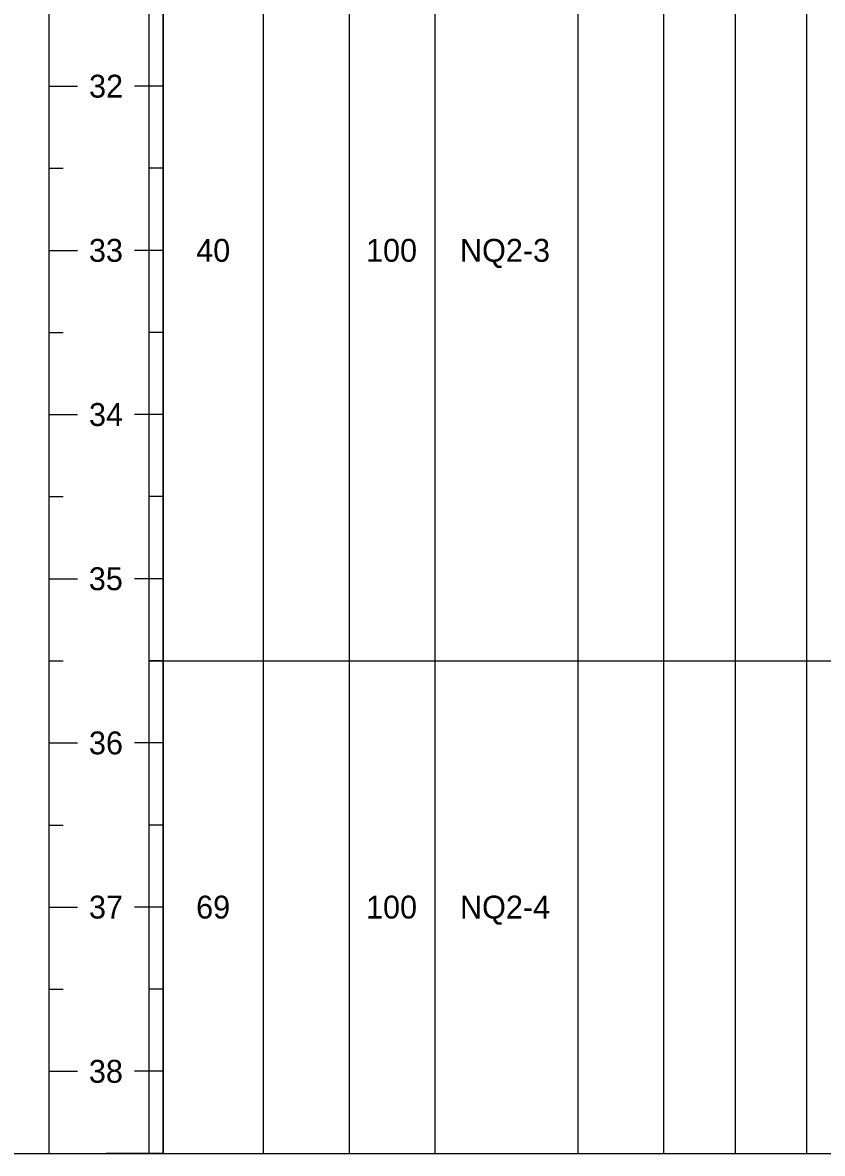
# Model space of a CAD drawing. Extents: x 0 to 0.83, y -0.65 to 1.27.
# Drawn here: x 0.3715 to 0.6046, y -0.6457 to -0.3163 of the extents above; entities that cross this region are included whole.
import ezdxf

# ---------------------------------------------------------------- set-up
doc = ezdxf.new("R2010")
doc.units = 0

msp = doc.modelspace()

# ---------------------------------------------------------------- linework, layer by layer
for points in [[(0.4125, 1.22083), (0.4125, -0.64575)], [(0.4125, 1.22083), (0.4125, -0.64575)], [(0.44167, 1.22083), (0.44167, -0.64575)], [(0.46667, 1.22083), (0.46667, -0.64575)], [(0.49167, 1.22083), (0.49167, -0.64575)], [(0.53333, 1.22083), (0.53333, -0.64575)], [(0.55833, 1.22083), (0.55833, -0.64575)], [(0.57917, 1.20833), (0.57917, -0.64575)], [(0.6, 1.20833), (0.6, -0.64575)], [(0.37917, 1.19583), (0.37917, -0.64575)], [(0.40833, -0.26308), (0.40833, -0.50225)], [(0.37917, -0.33483), (0.3875, -0.33483)], [(0.37917, -0.33483), (0.38333, -0.33483)], [(0.4125, -0.33483), (0.40417, -0.33483)], [(0.4125, -0.33483), (0.40833, -0.33483)], [(0.37917, -0.35875), (0.38333, -0.35875)], [(0.4125, -0.35875), (0.40833, -0.35875)], [(0.37917, -0.38267), (0.3875, -0.38267)], [(0.37917, -0.38267), (0.38333, -0.38267)], [(0.4125, -0.38267), (0.40417, -0.38267)], [(0.4125, -0.38267), (0.40833, -0.38267)], [(0.37917, -0.40658), (0.38333, -0.40658)], [(0.4125, -0.40658), (0.40833, -0.40658)], [(0.37917, -0.4305), (0.3875, -0.4305)], [(0.37917, -0.4305), (0.38333, -0.4305)], [(0.4125, -0.4305), (0.40417, -0.4305)], [(0.4125, -0.4305), (0.40833, -0.4305)], [(0.37917, -0.45442), (0.38333, -0.45442)], [(0.4125, -0.45442), (0.40833, -0.45442)], [(0.37917, -0.47833), (0.3875, -0.47833)], [(0.37917, -0.47833), (0.38333, -0.47833)], [(0.4125, -0.47833), (0.40417, -0.47833)], [(0.4125, -0.47833), (0.40833, -0.47833)], [(0.37917, -0.50225), (0.38333, -0.50225)], [(0.40833, -0.50225), (0.4125, -0.50225)], [(0.40833, -0.50225), (0.40833, -0.64575)], [(0.40833, -0.50225), (0.4125, -0.50225)], [(0.4125, -0.50225), (0.40833, -0.50225)], [(0.4125, -0.50225), (0.44167, -0.50225)], [(0.44167, -0.50225), (0.46667, -0.50225)], [(0.46667, -0.50225), (0.49167, -0.50225)], [(0.49167, -0.50225), (0.53333, -0.50225)], [(0.53333, -0.50225), (0.55833, -0.50225)], [(0.55833, -0.50225), (0.57917, -0.50225)], [(0.57917, -0.50225), (0.6, -0.50225)], [(0.6, -0.50225), (0.62083, -0.50225)], [(0.37917, -0.52617), (0.3875, -0.52617)], [(0.37917, -0.52617), (0.38333, -0.52617)], [(0.4125, -0.52617), (0.40417, -0.52617)], [(0.4125, -0.52617), (0.40833, -0.52617)], [(0.37917, -0.55008), (0.38333, -0.55008)], [(0.4125, -0.55008), (0.40833, -0.55008)], [(0.37917, -0.574), (0.3875, -0.574)], [(0.37917, -0.574), (0.38333, -0.574)], [(0.4125, -0.574), (0.40417, -0.574)], [(0.4125, -0.574), (0.40833, -0.574)], [(0.37917, -0.59792), (0.38333, -0.59792)], [(0.4125, -0.59792), (0.40833, -0.59792)], [(0.37917, -0.62183), (0.3875, -0.62183)], [(0.37917, -0.62183), (0.38333, -0.62183)], [(0.4125, -0.62183), (0.40417, -0.62183)], [(0.4125, -0.62183), (0.40833, -0.62183)], [(0.33333, -0.64575), (0.37917, -0.64575)], [(0.37917, -0.64575), (0.4125, -0.64575)], [(0.37917, -0.64575), (0.38333, -0.64575)], [(0.37917, -0.64575), (0.39583, -0.64575)], [(0.4125, -0.64575), (0.39583, -0.64575)], [(0.40833, -0.64575), (0.4125, -0.64575)], [(0.40833, -0.64575), (0.4125, -0.64575)], [(0.4125, -0.64575), (0.40833, -0.64575)], [(0.4125, -0.64575), (0.44167, -0.64575)], [(0.44167, -0.64575), (0.46667, -0.64575)], [(0.46667, -0.64575), (0.49167, -0.64575)], [(0.49167, -0.64575), (0.53333, -0.64575)], [(0.53333, -0.64575), (0.55833, -0.64575)], [(0.55833, -0.64575), (0.57917, -0.64575)], [(0.57917, -0.64575), (0.6, -0.64575)], [(0.6, -0.64575), (0.62083, -0.64575)]]:
    msp.add_lwpolyline(points)
for points in [[(0.40833, -0.50225), (0.4125, -0.50225), (0.4125, -0.26308), (0.40833, -0.26308)], [(0.40833, -0.64575), (0.4125, -0.64575), (0.4125, -0.50225), (0.40833, -0.50225)]]:
    msp.add_lwpolyline(points, close=True)

# ---------------------------------------------------------------- texts
for s, p in [('32', (0.3909, -0.33817)), ('33', (0.39087, -0.386)), ('40', (0.42213, -0.386)), ('100', (0.47162, -0.386)), ('NQ2-3', (0.499, -0.386)), ('34', (0.39088, -0.43383)), ('35', (0.39084, -0.48167)), ('36', (0.39087, -0.5295)), ('37', (0.39087, -0.57733)), ('69', (0.42211, -0.57733)), ('100', (0.47162, -0.57733)), ('NQ2-4', (0.49901, -0.57733)), ('38', (0.39086, -0.62517))]:
    msp.add_text(s, height=0.006667).set_placement(p)

doc.saveas('drawing.dxf')
